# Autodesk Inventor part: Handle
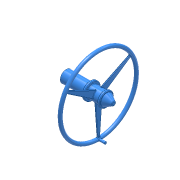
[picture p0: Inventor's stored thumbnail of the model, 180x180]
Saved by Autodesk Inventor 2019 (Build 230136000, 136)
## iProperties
Created: 2018-04
Part Number: Handle
Material: 一般
Document SubType Name: Modeling
Designer: ADJ
Density: 1 g/cm^3
Appearance: シアン
Mass: 605.042 g
Surface Area: 1027.35 cm^2
Volume: 605.042 cm^3
Author: ADJ
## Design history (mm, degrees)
sketch "スケッチ1"
  geometry: L1 (0, 0)-(0, 25); L2 (0, 25)-(100, 25); L3 (100, 25)-(100, 35); L4 (100, 35)-(110, 35); L5 (110, 35)-(110, 25); L6 (110, 25)-(160, 25); L7 (160, 25)-(160, 30); L8 (160, 30)-(170, 30); L9 (170, 30)-(170, 25); L10 (170, 25)-(170.555, 25); L11 (170.555, 25)-(200, 8); L12 (200, 8)-(200, 0); L13 (200, 0)-(0, 0)
  constraints: 26 end point, 8 perpendicular, 4 point on line, 1 parallel, 1 vertical
  dimensions: "d0" = 100 distance between parallel lines of L3 L1; "d1" = 10 distance of L3.end L4.end; "d2" = 50 distance of L5.end L6.end; "d3" = 10 distance of L7.end L8.end; "d4" = 0.55498 distance of L9.end L10.end; "d5" = 200 distance between parallel lines of L1 L12; "d6" = 30 deg angle of L13 L11; "d7" = 25 distance between parallel lines of L13 L2; "d8" = 10 distance between parallel lines of L2 L4; "d9" = 5 distance between parallel lines of L6 L8
revolve "回転1" sketch "スケッチ1" stored, may be unused: angle "d10" = 90 deg
sketch "スケッチ2"
  geometry: L1 (40, 0)-(-240, 0) reference; C1 r 7.5 at (-135, -160); 1 further point
  constraints: 1 centre point
  dimensions: "d11" = 15 diameter of C1; "d12" = 160 vertical distance of point (0, 0) C1.centre; "d13" = 135 horizontal distance of point (0, 0) C1.centre
revolve "回転2" sketch "スケッチ2" stored, may be unused: angle "d14" = 90 deg
node "作業平面1"
sketch "スケッチ3"
  geometry: L1 (-156.233, 5)-(-156.233, -5); L2 (-156.233, -5)-(-16.233, -15); L3 (-16.233, -15)-(-16.233, 15); L4 (-16.233, 15)-(-156.233, 5); L5 (-156.233, 0)-(-16.233, 0); L6 (-130.955, 0)-(123.909, 0) reference; 1 further point
  constraints: 10 end point, 2 midpoint, 1 collinear, 1 parallel, 1 perpendicular, 1 vertical, 1 other
  dimensions: "d16" = 10 distance of L1.start L1.end; "d17" = 30 distance of L2.end L3.end; "d18" = 140 distance between parallel lines of L1 L3
extrude "押し出し1" join sketch "スケッチ3" stored distance "d19" = 5; taper "d20" = 0 deg
pattern_circular "円形状パターン1" dims angle "d22" = 360 deg
sketch "スケッチ4"
  geometry: C1 r 5 at (-160, 0); 1 further point
  constraints: 1 centre point
  dimensions: "d24" = 10 diameter of C1; "d35" = 160 distance of point (0, 0) C1.centre
extrude "押し出し2" join sketch "スケッチ4" distance "d25" = 30; taper "d26" = 0 deg
fillet "フィレット1" dims "d27" = 2
chamfer "面取り1" distance "d28" = 2; stored, may be unused: second distance "d29" = 2, angle "d30" = 45 deg
fillet "フィレット2" dims "d31" = 2
chamfer "面取り2" distance "d32" = 2; stored, may be unused: second distance "d33" = 2, angle "d34" = 45 deg
node "ソリッド1"
other parameters: "d15" = -135
